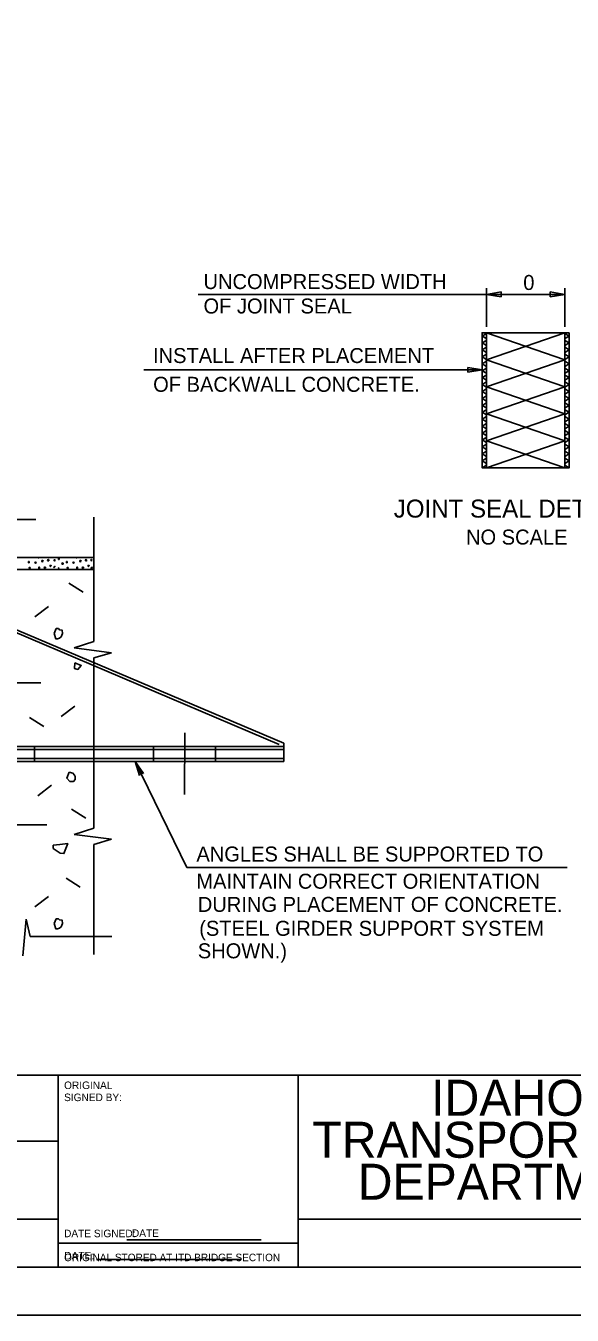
# Model space of a CAD drawing. Extents: x 0 to 11.3, y 0 to 7.8.
# Drawn here: x 3.721 to 5.617, y 0 to 4.478 of the extents above; entities that cross this region are included whole.
import ezdxf

# ---------------------------------------------------------------- set-up
doc = ezdxf.new("R2010")
doc.units = 0
for name, color, linetype in [('BORDER_ANNO_Cutsheet', 7, 'Continuous'), ('BRDG_ANNO_Anno-Large-Print', 7, 'Continuous'), ('BRDG_ANNO_Anno-Sheet', 7, 'Continuous'), ('BRDG_ANNO_Anno-Small-Print', 7, 'Continuous'), ('BRDG_ANNO_General-Notes', 7, 'Continuous'), ('BRDG_BASE_Dtlctrln', 7, 'Continuous'), ('BRDG_BASE_Hidden-Line', 7, 'Continuous'), ('BRDG_BASE_Obj-Line', 7, 'Continuous'), ('BRDG_BASE_Pattern', 7, 'Continuous')]:
    doc.layers.add(name, color=color, linetype=linetype)

msp = doc.modelspace()

# ---------------------------------------------------------------- linework, layer by layer
at = {"layer": 'BORDER_ANNO_Cutsheet'}
msp.add_lwpolyline([(0, 7.3333), (11.3333, 7.3333), (11.3333, 0), (0, 0)], close=True, dxfattribs=at)
at = {"layer": 'BRDG_ANNO_Anno-Large-Print'}
msp.add_line((3.9665, 0.1935), (4.4685, 0.1935), dxfattribs=at)
at = {"layer": 'BRDG_ANNO_Anno-Sheet'}
for p, q in [((0.5, 0.8333), (6.4167, 0.8333)), ((3.8333, 0.1667), (3.8333, 0.8333)), ((4.6667, 0.1667), (4.6667, 0.8333)), ((3.1667, 0.6042), (3.8333, 0.6042)), ((3.1667, 0.3333), (3.8333, 0.3333)), ((4.6667, 0.3333), (6.4167, 0.3333))]:
    msp.add_line(p, q, dxfattribs=at)
msp.add_lwpolyline([(0.5, 7.1667), (11.1667, 7.1667), (11.1667, 0.1667), (0.5, 0.1667)], close=True, dxfattribs=at)
at = {"layer": 'BRDG_ANNO_Anno-Small-Print'}
for p, q in [((3.8333, 0.25), (4.6667, 0.25)), ((4.0721, 0.2621), (4.5379, 0.2621))]:
    msp.add_line(p, q, dxfattribs=at)
at = {"layer": 'BRDG_ANNO_General-Notes'}
for p, q in [((4.3193, 3.5453), (5.3204, 3.5453)), ((5.3204, 3.433), (5.3204, 3.5668)), ((5.3204, 3.5453), (5.3704, 3.5536)), ((5.3204, 3.5453), (5.5912, 3.5453)), ((5.3704, 3.537), (5.3204, 3.5453)), ((5.3704, 3.5536), (5.3704, 3.537)), ((5.5412, 3.537), (5.5412, 3.5536)), ((5.5412, 3.5536), (5.5912, 3.5453)), ((5.5912, 3.5453), (5.5412, 3.537)), ((5.5912, 3.433), (5.5912, 3.5668)), ((4.1313, 3.2835), (5.3047, 3.2835)), ((5.2547, 3.2752), (5.2547, 3.2919)), ((5.2547, 3.2919), (5.3047, 3.2835)), ((5.3047, 3.2835), (5.2547, 3.2752)), ((3.7564, 2.7631), (3.2173, 2.7631)), ((4.2806, 1.5552), (4.1007, 1.9231)), ((4.1007, 1.9231), (4.1155, 1.8746)), ((4.1007, 1.9231), (4.1298, 1.8816)), ((3.7941, 1.7036), (3.1774, 1.7036)), ((5.5999, 1.5552), (4.2806, 1.5552))]:
    msp.add_line(p, q, dxfattribs=at)
msp.add_arc((4.1244, 1.8747), 0.00882, 51.2965, 180.861, dxfattribs=at)
at = {"layer": 'BRDG_BASE_Dtlctrln'}
for p, q in [((2.9021, 2.1974), (3.7739, 2.1963)), ((4.2728, 2.022), (4.2726, 1.8083))]:
    msp.add_line(p, q, dxfattribs=at)
at = {"layer": 'BRDG_BASE_Hidden-Line'}
for p, q in [((3.2821, 2.542), (4.6009, 1.9822)), ((3.2861, 2.5516), (4.6168, 1.9868)), ((3.3156, 1.9752), (4.6168, 1.9752)), ((3.7514, 1.9735), (3.7514, 1.9214)), ((4.1643, 1.9735), (4.1643, 1.9214)), ((4.3793, 1.9735), (4.3793, 1.9214)), ((4.6168, 1.9868), (4.6168, 1.9231)), ((3.3161, 1.9648), (4.6174, 1.9648)), ((3.3161, 1.9335), (4.6168, 1.9335)), ((3.3156, 1.9231), (4.6168, 1.9231))]:
    msp.add_line(p, q, dxfattribs=at)
at = {"layer": 'BRDG_BASE_Obj-Line'}
for p, q in [((3.958, 2.3396), (3.958, 2.7711)), ((3.3648, 2.6315), (3.958, 2.6315)), ((3.2901, 2.5903), (3.958, 2.5903)), ((3.958, 2.3396), (3.8897, 2.3174)), ((3.8897, 2.3174), (4.0192, 2.3003)), ((4.0192, 2.3003), (3.958, 2.2829)), ((3.958, 1.692), (3.958, 2.2829)), ((3.958, 1.692), (3.8897, 1.6698)), ((3.8897, 1.6698), (4.0192, 1.6528)), ((4.0192, 1.6528), (3.958, 1.6353)), ((3.958, 1.2523), (3.958, 1.6353)), ((3.7105, 1.2484), (3.7231, 1.376)), ((3.7231, 1.376), (3.7361, 1.3157)), ((4.0197, 1.3157), (3.7361, 1.3157))]:
    msp.add_line(p, q, dxfattribs=at)
for points in [[(5.3204, 3.4122), (5.3047, 3.4122), (5.3047, 2.9434), (5.3204, 2.9434)], [(5.3204, 3.4122), (5.5912, 3.4122), (5.5912, 2.9434), (5.3204, 2.9434)], [(5.6068, 3.4122), (5.5912, 3.4122), (5.5912, 2.9434), (5.6068, 2.9434)]]:
    msp.add_lwpolyline(points, close=True, dxfattribs=at)
at = {"layer": 'BRDG_BASE_Pattern'}
for p, q in [((5.3047, 3.4005), (5.3204, 3.4095)), ((5.3204, 3.4122), (5.5912, 3.3184)), ((5.3204, 3.3184), (5.5912, 3.4122)), ((5.6068, 3.4005), (5.5912, 3.4095)), ((5.3204, 3.3915), (5.3047, 3.4005)), ((5.3047, 3.3765), (5.3204, 3.3855)), ((5.3204, 3.3674), (5.3047, 3.3765)), ((5.3047, 3.3524), (5.3204, 3.3614)), ((5.5912, 3.3915), (5.6068, 3.4005)), ((5.6068, 3.3765), (5.5912, 3.3855)), ((5.5912, 3.3674), (5.6068, 3.3765)), ((5.6068, 3.3524), (5.5912, 3.3614)), ((5.3204, 3.3434), (5.3047, 3.3524)), ((5.3047, 3.3283), (5.3204, 3.3373)), ((5.3204, 3.3193), (5.3047, 3.3283)), ((5.3204, 3.2247), (5.5912, 3.3184)), ((5.3204, 3.3184), (5.5912, 3.2247)), ((5.5912, 3.3434), (5.6068, 3.3524)), ((5.6068, 3.3283), (5.5912, 3.3373)), ((5.5912, 3.3193), (5.6068, 3.3283)), ((5.3047, 3.3043), (5.3204, 3.3133)), ((5.3204, 3.2953), (5.3047, 3.3043)), ((5.3047, 3.2802), (5.3204, 3.2893)), ((5.3204, 3.2712), (5.3047, 3.2802)), ((5.6068, 3.3043), (5.5912, 3.3133)), ((5.5912, 3.2953), (5.6068, 3.3043)), ((5.6068, 3.2802), (5.5912, 3.2893)), ((5.5912, 3.2712), (5.6068, 3.2802)), ((5.3047, 3.2561), (5.3204, 3.2652)), ((5.3204, 3.2471), (5.3047, 3.2561)), ((5.3047, 3.2321), (5.3204, 3.2411)), ((5.3204, 3.2231), (5.3047, 3.2321)), ((5.3204, 3.2247), (5.5912, 3.1309)), ((5.3204, 3.1309), (5.5912, 3.2247)), ((5.6068, 3.2561), (5.5912, 3.2652)), ((5.5912, 3.2471), (5.6068, 3.2561)), ((5.6068, 3.2321), (5.5912, 3.2411)), ((5.5912, 3.2231), (5.6068, 3.2321)), ((5.3047, 3.2081), (5.3204, 3.2171)), ((5.3204, 3.199), (5.3047, 3.2081)), ((5.3047, 3.184), (5.3204, 3.193)), ((5.3204, 3.175), (5.3047, 3.184)), ((5.6068, 3.2081), (5.5912, 3.2171)), ((5.5912, 3.199), (5.6068, 3.2081)), ((5.6068, 3.184), (5.5912, 3.193)), ((5.5912, 3.175), (5.6068, 3.184)), ((5.3047, 3.1599), (5.3204, 3.169)), ((5.3204, 3.1509), (5.3047, 3.1599)), ((5.3047, 3.1359), (5.3204, 3.1449)), ((5.3204, 3.1269), (5.3047, 3.1359)), ((5.6068, 3.1599), (5.5912, 3.169)), ((5.5912, 3.1509), (5.6068, 3.1599)), ((5.6068, 3.1359), (5.5912, 3.1449)), ((5.5912, 3.1269), (5.6068, 3.1359)), ((5.3047, 3.1118), (5.3204, 3.1208)), ((5.3204, 3.1028), (5.3047, 3.1118)), ((5.3047, 3.0878), (5.3204, 3.0968)), ((5.3204, 3.0372), (5.5912, 3.1309)), ((5.3204, 3.1309), (5.5912, 3.0372)), ((5.6068, 3.1118), (5.5912, 3.1208)), ((5.5912, 3.1028), (5.6068, 3.1118)), ((5.6068, 3.0878), (5.5912, 3.0968)), ((5.3204, 3.0787), (5.3047, 3.0878)), ((5.3047, 3.0637), (5.3204, 3.0728)), ((5.3204, 3.0547), (5.3047, 3.0637)), ((5.3047, 3.0397), (5.3204, 3.0487)), ((5.5912, 3.0787), (5.6068, 3.0878)), ((5.6068, 3.0637), (5.5912, 3.0728)), ((5.5912, 3.0547), (5.6068, 3.0637)), ((5.6068, 3.0397), (5.5912, 3.0487)), ((5.3204, 3.0306), (5.3047, 3.0397)), ((5.3047, 3.0156), (5.3204, 3.0246)), ((5.3204, 3.0066), (5.3047, 3.0156)), ((5.3047, 2.9916), (5.3204, 3.0006)), ((5.3204, 3.0372), (5.5912, 2.9434)), ((5.3204, 2.9434), (5.5912, 3.0372)), ((5.5912, 3.0306), (5.6068, 3.0397)), ((5.6068, 3.0156), (5.5912, 3.0246)), ((5.5912, 3.0066), (5.6068, 3.0156)), ((5.6068, 2.9916), (5.5912, 3.0006)), ((5.3204, 2.9826), (5.3047, 2.9916)), ((5.3047, 2.9675), (5.3204, 2.9765)), ((5.3204, 2.9585), (5.3047, 2.9675)), ((5.5912, 2.9826), (5.6068, 2.9916)), ((5.6068, 2.9675), (5.5912, 2.9765)), ((5.5912, 2.9585), (5.6068, 2.9675)), ((5.3047, 2.9434), (5.3204, 2.9524)), ((5.6068, 2.9434), (5.5912, 2.9524)), ((3.8706, 2.5422), (3.9201, 2.511)), ((3.8004, 2.4616), (3.7523, 2.425)), ((3.8918, 2.1155), (3.8437, 2.0789)), ((3.7346, 2.0756), (3.7842, 2.0444)), ((3.8107, 1.8407), (3.7626, 1.8041)), ((3.8796, 1.7575), (3.9292, 1.7262)), ((3.8609, 1.5174), (3.9104, 1.4861)), ((3.8004, 1.4543), (3.7523, 1.4177))]:
    msp.add_line(p, q, dxfattribs=at)
for points in [[(3.8197, 2.3678), (3.8255, 2.3493), (3.8308, 2.3493), (3.8383, 2.3511), (3.8438, 2.3565), (3.8491, 2.3678), (3.8476, 2.3787), (3.8383, 2.3806), (3.8344, 2.3844), (3.8271, 2.3844)], [(3.8914, 2.2653), (3.8905, 2.2455), (3.9024, 2.2428), (3.914, 2.2561)], [(3.8724, 1.8856), (3.8632, 1.8654), (3.874, 1.8541), (3.8872, 1.8541), (3.8927, 1.86), (3.8927, 1.8708), (3.8908, 1.8761), (3.8851, 1.882)], [(3.8389, 1.6343), (3.8168, 1.6324), (3.8168, 1.6214), (3.8408, 1.6048), (3.8537, 1.603), (3.8667, 1.6379)], [(3.8197, 1.3604), (3.8255, 1.342), (3.8308, 1.342), (3.8383, 1.3438), (3.8438, 1.3492), (3.8491, 1.3604), (3.8476, 1.3714), (3.8383, 1.3733), (3.8344, 1.3771), (3.8271, 1.3771)]]:
    msp.add_lwpolyline(points, close=True, dxfattribs=at)
for centre in [(3.7793, 2.619), (3.7876, 2.5958), (3.799, 2.6222), (3.8491, 2.6104), (3.9111, 2.619), (3.9194, 2.5958), (3.9308, 2.6222)]:
    msp.add_circle(centre, 0.00244, dxfattribs=at)
for centre in [(3.7656, 2.6331), (3.8974, 2.6331)]:
    msp.add_arc(centre, 0.00244, 222.2523, 317.7476, dxfattribs=at)
for centre, major_axis in [((3.7317, 2.6154), (0, -0.00275)), ((3.7552, 2.6135), (0.00275, 0)), ((3.7675, 2.5958), (0, -0.00275)), ((3.8074, 2.6023), (-0.00195, -0.00195)), ((3.8203, 2.5986), (-0.00195, -0.00195)), ((3.8213, 2.6215), (0, -0.00275)), ((3.8362, 2.627), (0, -0.00275)), ((3.8636, 2.6154), (0, -0.00275)), ((3.887, 2.6135), (0.00275, 0)), ((3.8993, 2.5958), (0, -0.00275)), ((3.9392, 2.6023), (-0.00195, -0.00195)), ((3.9488, 2.6223), (0, -0.00275)), ((3.9502, 2.5958), (-0.00195, -0.00195)), ((3.7347, 2.5957), (0.00275, 0)), ((3.8666, 2.5957), (0.00275, 0))]:
    msp.add_ellipse(centre, major_axis=major_axis, ratio=0.5, dxfattribs=at)
msp.add_ellipse((3.8354, 2.593), major_axis=(0, -0.00275), ratio=0.5, start_param=0.00615, end_param=6.277035, dxfattribs=at)

# ---------------------------------------------------------------- texts
at = {"layer": 'BRDG_ANNO_Anno-Large-Print'}
msp.add_text('DATE:', height=0.02624, dxfattribs=at).set_placement((3.855, 0.1935))
at = {"layer": 'BRDG_ANNO_Anno-Sheet'}
for s, p in [('IDAHO', (5.1279, 0.6927)), ('TRANSPORTATION', (4.7156, 0.5469)), ('DEPARTMENT', (4.8731, 0.401))]:
    msp.add_text(s, height=0.125, dxfattribs=at).set_placement(p)
at = {"layer": 'BRDG_ANNO_Anno-Small-Print'}
for s, height, p in [('ORIGINAL', 0.02625, (3.8542, 0.7854)), ('SIGNED BY:', 0.02625, (3.8542, 0.7435)), ('DATE SIGNED:', 0.02625, (3.8542, 0.2708)), ('DATE', 0.02624, (4.0896, 0.2719)), ('ORIGINAL STORED AT ITD BRIDGE SECTION', 0.026072, (3.8542, 0.1876))]:
    msp.add_text(s, height=height, dxfattribs=at).set_placement(p)
at = {"layer": 'BRDG_ANNO_General-Notes'}
for s, height, p in [('UNCOMPRESSED WIDTH', 0.052083, (4.338, 3.5638)), ('0', 0.0521, (5.4475, 3.5606)), ('OF JOINT SEAL', 0.052083, (4.338, 3.4789)), ('INSTALL AFTER PLACEMENT', 0.052083, (4.1628, 3.3068)), ('OF BACKWALL CONCRETE.', 0.052083, (4.1633, 3.2069)), ('JOINT SEAL DETAIL', 0.0625, (4.9981, 2.7701)), ('NO SCALE', 0.05208, (5.2488, 2.6764)), ('ANGLES SHALL BE SUPPORTED TO', 0.052083, (4.3134, 1.5756)), ('MAINTAIN CORRECT ORIENTATION', 0.052083, (4.3132, 1.4812)), ('DURING PLACEMENT OF CONCRETE.', 0.052083, (4.3183, 1.4007)), ('(STEEL GIRDER SUPPORT SYSTEM', 0.052083, (4.3232, 1.3176)), ('SHOWN.)', 0.05208, (4.3182, 1.2395))]:
    msp.add_text(s, height=height, dxfattribs=at).set_placement(p)

doc.saveas('drawing.dxf')
